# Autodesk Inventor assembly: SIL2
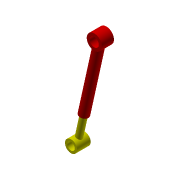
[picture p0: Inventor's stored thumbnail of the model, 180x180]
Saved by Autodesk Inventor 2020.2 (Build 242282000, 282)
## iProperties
Manager: www.cadconsulting.pl
Company: Fabian Stasiak CAD Consulting
Created: 2005-10
Part Number: SIL2
Document SubType Name: Assembly
Designer: F.Stasiak
Author: F.Stasiak
Subject: Zbiór ćwiczeń. Autodesk Inventor 2020. Kurs podstawowy
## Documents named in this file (3)
- C:\2020_Kurs_podstawowy\R6 Zespoły\Lustro\SIL2.iam
- C:\2020_Kurs_podstawowy\R6 Zespoły\Lustro\Cyl2.ipt
- C:\2020_Kurs_podstawowy\R6 Zespoły\Lustro\T2.ipt
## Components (2 placed, 2 different names)
1. Cyl2:1
2. T2:1
